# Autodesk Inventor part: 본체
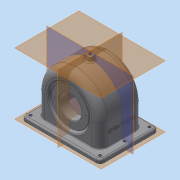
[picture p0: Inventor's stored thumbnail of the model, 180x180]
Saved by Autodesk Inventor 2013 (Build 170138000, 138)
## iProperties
Created: 2015-09
Part Number: 본체
Material: 일반
Document SubType Name: Modeling
Designer: Administrator
Density: 1 g/cm^3
Author: Administrator
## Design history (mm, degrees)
sketch "스케치1"
  geometry: L1 (-70, -52)-(70, -52); L2 (70, -52)-(70, 52); L3 (70, 52)-(-70, 52); L4 (-70, 52)-(-70, -52); 3 further points
  constraints: 8 end point, 2 midpoint, 2 parallel, 1 horizontal, 1 horizontal alignment, 1 perpendicular, 1 vertical alignment
  dimensions: "d0" = 140 distance of L2.end L3.end; "d2" = 104 distance of L1.end L2.end
extrude "돌출1" new body sketch "스케치1" distance "d3" = 7; taper "d4" = 0 deg
sketch "스케치2"
  geometry: L1 (70, 7)-(-70, 7) reference; L2 (51, 7)-(51, 47); L3 (-51, 7)-(-51, 47); L4 (51, 47)-(-51, 47); L5 (70, 0)-(-70, 0) reference; L6 (-56, 47)-(-56, 41.907); L7 (-56, 41.907)-(-56, 7); L8 (56, 47)-(56, 7); A1 r 51 centre (0, 47) between (51, 47) and (-51, 47); A2 r 56 centre (0, 47) between (56, 47) and (-56, 47); 3 further points
  constraints: 12 end point, 5 perpendicular, 4 point on circle, 4 point on line, 3 tangent, 2 centre point, 2 midpoint, 1 parallel, 1 vertical alignment
  dimensions: "d6" = 51 radius of A1; "d7" = 47 distance from line of L3.end L5; "d26" = 5 radial gap between concentric circles of A2 A1
extrude "돌출5" join sketch "스케치2" stored distance "d27" = 77; taper "d28" = 0 deg
node "작업 평면2"
sketch "스케치7"
  geometry: C1 r 20 at (0, -47); A1 r 56 centre (0, -47) between (-56, -47) and (56, -47) reference; 1 further point
  constraints: 1 centre point, 1 coincident
  dimensions: "d34" = 40 diameter of C1
extrude "돌출7" cut sketch "스케치7" stored distance "d36" = 77; taper "d37" = 0 deg
sketch "스케치8"
  geometry: L1 (51, 7)-(51, 47) reference; L2 (70, 7)-(-70, 7) reference; L3 (-51, 7)-(-51, 47) reference; A1 r 51 centre (0, 47) between (51, 47) and (-51, 47) reference; 2 further points
extrude "돌출8" cut sketch "스케치8" stored distance "d38" = 67; taper "d39" = 0 deg
sketch "스케치10"
  geometry: C1 r 20 at (0, -47) reference; C2 r 31 at (0, -47); 1 further point
  constraints: 1 centre point, 1 coincident
  dimensions: "d41" = 62 diameter of C2
extrude "돌출9" join sketch "스케치10" distance "d44" = 10; taper "d45" = 0 deg
node "작업 평면4"
sketch "스케치11"
  geometry: L1 (-35.5, 132)-(-35.5, -22) reference; L2 (-35.5, 88.426)-(-19.5, 75); L3 (-19.5, 75)-(-19.5, 47); L4 (-19.5, 47)-(-35.5, 47); L5 (52, 0)-(-52, 0) reference; 1 further point
  constraints: 6 end point, 2 point on line, 1 perpendicular, 1 vertical alignment
  dimensions: "d48" = 50 deg angle of L3 L2; "d49" = 47 distance from line of L4.end L5; "d50" = 16 distance of L3.end L4.end; "d51" = 56 diameter of L2.end L4
revolve "회전1" sketch "스케치11" stored, may be unused: angle "d52" = 90 deg
sketch "스케치13"
  geometry: L1 (-33.5, 86.747)-(-19.5, 75) reference; L2 (-38.5, 9.584)-(-35.5, 12.101); L3 (-38.5, 103)-(-38.5, 47) reference; L4 (-33.5, 47)-(33.5, 47) reference; L5 (-33.5, 47)-(-33.5, 47) reference; L6 (33.5, 47)-(-33.5, 47) reference; L7 (33.5, 47)-(33.5, 47) reference; L8 (-38.5, 84.416)-(-24.756, 72.883); L9 (-24.756, 72.883)-(-24.756, 47); L10 (-38.5, 47)-(-38.5, 84.416); L11 (-38.5, 47)-(-24.756, 47); 1 further point
  constraints: 11 end point, 2 point on line, 1 collinear, 1 parallel, 1 perpendicular
  dimensions: "d60" = 5 distance from line of L1 L8.end
revolve "회전2" sketch "스케치13" stored, may be unused: angle "d61" = 90 deg
node "작업 평면5"
sketch "스케치14"
  geometry: C1 r 33 at (0, 47); A1 r 56 centre (0, 47) between (56, 47) and (-56, 47) reference; 1 further point
  constraints: 1 centre point, 1 coincident
  dimensions: "d63" = 66 diameter of C1
extrude "돌출11" join sketch "스케치14" stored distance "d65" = 5; taper "d66" = 0 deg
sketch "스케치15"
  geometry: C1 r 33 at (0, 0) reference; A1 r 28 centre (0, 0) between (0, 28) and (-28, 0); 3 further points
  constraints: 4 point on circle, 1 centre point, 1 coincident
  dimensions: "d67" = 56 diameter of A1
hole "구멍2" sketch "스케치15" at (0, 28), (-28, 0), (0, -28), (28, 0) diameter "d69" = 2.459; stored, may be unused: countersink angle "d73" = 90 deg, drill point angle "d75" = 118 deg; dims "d70" = 7, "d71" = 4, "d72" = 2, "d74" = 9
sketch "스케치16"
  geometry: C1 r 20 at (0, 0); A1 r 56 centre (0, 0) between (56, 0) and (-56, 0) reference; 1 further point
  constraints: 1 centre point, 1 coincident
  dimensions: "d76" = 40 diameter of C1
extrude "돌출12" cut sketch "스케치16" stored distance "d78" = 5; taper "d79" = 0 deg
fillet "모깎기1" dims "d80" = 0.5
sketch "스케치19"
  geometry: L1 (-2.826, 16.342)-(-2.826, 42.658); L2 (-2.826, 42.658)-(36.826, 42.658); L3 (36.826, 42.658)-(36.826, 16.342); L4 (36.826, 16.342)-(-2.826, 16.342); L5 (36.826, 16.342)-(-2.826, 42.658); L6 (-85, 29.5)-(69, 29.5) reference; L7 (0, -9)-(40, -9) reference; L8 (47, -22.5)-(47, 81.5) reference; 2 further points
  constraints: 2 end point, 1 midpoint, 2 other
  dimensions: "d86" = 38.5 distance from line of point (17, 29.5) L7; "d87" = 30 distance from line of point (17, 29.5) L8
feature "엠보싱1" sketch "스케치19" dims "d88" = 0.5, "d89" = 0
sketch "스케치20"
  geometry: L1 (-70, 52)-(-70, -52) reference; L2 (70, 52)-(-70, 52) reference; C1 r 2.5 at (-62, 44); C2 r 2.5 at (-62, 0); C3 r 2.5 at (-62, -44); 1 further point
  constraints: 3 centre point, 2 vertical alignment
  dimensions: "d90" = 5 diameter of C1; "d92" = 5 diameter of C2; "d93" = 44 distance of C1.centre C2.centre; "d94" = 44 distance of C2.centre C3.centre; "d95" = 8 distance from line of L1 C1.centre; "d96" = 8 distance from line of L2 C1.centre; "d97" = 5 diameter of C3
extrude "돌출13" cut sketch "스케치20" stored distance "d98" = 49; taper "d99" = 0 deg
fillet "모깎기4" dims "d100" = 7
sketch "스케치21"
  geometry: C1 r 31 at (0, 0) reference; A1 r 24 centre (0, 0) between (0, 24) and (-24, 0); 3 further points
  constraints: 4 point on circle, 1 centre point, 1 coincident
  dimensions: "d101" = 48 diameter of A1
hole "구멍3" sketch "스케치21" at (0, -24), (-24, 0), (24, 0), (0, 24) diameter "d103" = 2.459; stored, may be unused: countersink angle "d107" = 90 deg, drill point angle "d109" = 118 deg; dims "d104" = 6, "d105" = 4, "d106" = 2, "d108" = 8
fillet "모깎기6" dims "d111" = 3
fillet "모깎기7" dims "d112" = 3
sketch "스케치22"
  geometry: L1 (-38.5, 103)-(38.5, 103) reference; L2 (-6, 110)-(0, 110); L3 (0, 110)-(0, 98); L4 (0, 98)-(-8.116, 98); L5 (-33.5, 98)-(33.5, 98) reference; L6 (-8.116, 98)-(-6, 110); L7 (45, 0)-(-45, 0) reference; 1 further point
  constraints: 8 end point, 2 vertical alignment, 1 horizontal alignment, 1 midpoint, 1 parallel
  dimensions: "d114" = 12 diameter of L2.start L3; "d116" = 100 deg angle of L2 L6; "d118" = 110 distance from line of L2.start L7
fillet "모깎기9" dims "d119" = 9
fillet "모깎기10" dims "d120" = 14
fillet "모깎기11" dims "d121" = 1
revolve "회전3" stored, may be unused: angle "d122" = 90 deg
fillet "모깎기12" dims "d123" = 3
sketch "스케치23"
  geometry: 2 further points
  constraints: 1 coincident
hole "구멍4" sketch "스케치23" at (0, 0) diameter "d124" = 4.134; stored, may be unused: countersink angle "d128" = 90 deg, drill point angle "d130" = 0 deg; dims "d125" = 15, "d126" = 4, "d127" = 2, "d129" = 15
chamfer "모따기1" distance "d131" = 1; stored, may be unused: second distance "d132" = 2, angle "d133" = 45 deg
chamfer "모따기2" distance "d134" = 1; stored, may be unused: second distance "d135" = 2, angle "d136" = 45 deg
node "솔리드1"
mirror "대칭1"
node "투영된 루프1"
other parameters: "d47" = -84, "d62" = -3
